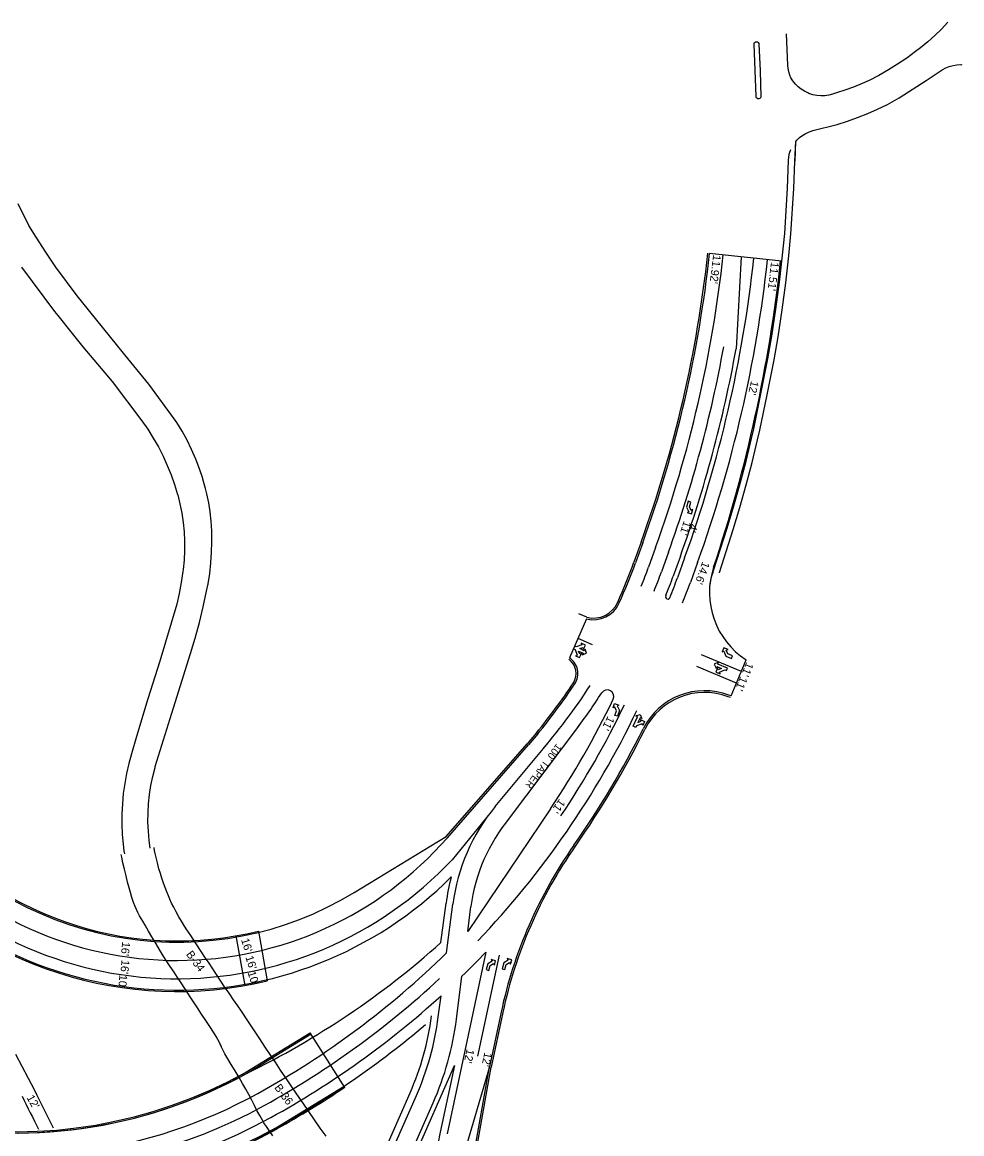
# Model space of a CAD drawing. Extents: x -5665 to 1997148, y 4 to 812485.
# Drawn here: x 1971217 to 1972039, y 796097 to 797070 of the extents above; entities that cross this region are included whole.
import ezdxf

# ---------------------------------------------------------------- set-up
doc = ezdxf.new("R2010")
doc.units = 0
for name, color, linetype in [('BR_CONCRETE', 7, 'Continuous'), ('RD_EX_Conc', 7, 'Continuous'), ('RD_EX_Road', 7, 'Continuous'), ('RD_PD_ALT1_TrvlWay', 7, 'Continuous'), ('RD_PD_Final_LnLine', 7, 'Continuous'), ('RD_PD_FOC', 7, 'Continuous'), ('RD_PD_PaintMed', 7, 'Continuous'), ('RD_PD_PaveShd', 7, 'Continuous'), ('RD_SHT_TX', 7, 'Continuous')]:
    doc.layers.add(name, color=color, linetype=linetype)

msp = doc.modelspace()

# ---------------------------------------------------------------- linework, layer by layer
at = {"layer": 'BR_CONCRETE'}
for p, q in [((1971423.24, 796274.72), (1971430.93, 796231.05)), ((1971403.67, 796270.59), (1971411.35, 796227.01)), ((1971412.3, 796151.25), (1971468.7, 796185.76)), ((1971412.98, 796150.14), (1971469.39, 796184.66)), ((1971499.08, 796137.98), (1971468.7, 796185.76)), ((1971439.09, 796102.88), (1971498.39, 796139.08))]:
    msp.add_line(p, q, dxfattribs=at)
for centre, radius, start, end in [((1971352.19, 796562.97), 296.88, 221.21202, 283.84721), ((1971352.19, 796562.97), 341.12, 221.21202, 283.34585), ((1971352.19, 796562.97), 340, 221.21202, 314.87827), ((1971210.82, 796516.01), 418, 222.88665, 298.92325), ((1971210.82, 796516.01), 416.88, 222.88665, 298.92325), ((1971051.22, 796804.85), 803.12, 298.92325, 303.88587), ((1971210.82, 796516.01), 473.13, 234.98689, 298.92325), ((1971210.82, 796516.01), 472, 234.98689, 298.92325), ((1971210.82, 796516.01), 473.3, 235.20921, 298.92325)]:
    msp.add_arc(centre, radius, start, end, dxfattribs=at)
at = {"layer": 'RD_EX_Conc'}
for points in [[(1972026.86, 797069.78), (1972021.28, 797063.78), (1972015.42, 797058.05), (1972009.29, 797052.61), (1972002.9, 797047.48), (1971998.4, 797044.15), (1971990.71, 797038.45), (1971982.79, 797033.07), (1971974.65, 797028.02), (1971966.31, 797023.31), (1971957.78, 797018.94), (1971951.78, 797016.13), (1971944.21, 797012.98), (1971936.51, 797010.2), (1971929.18, 797007.93), (1971925.88, 797006.71), (1971922.46, 797005.86), (1971918.97, 797005.4), (1971915.45, 797005.34), (1971911.95, 797005.66), (1971908.5, 797006.38), (1971905.16, 797007.48), (1971904.2, 797007.87), (1971901.14, 797009.34), (1971898.28, 797011.14), (1971895.64, 797013.27), (1971893.27, 797015.7), (1971892.25, 797017.02), (1971891.19, 797018.38), (1971889.45, 797021.28), (1971888.38, 797023.54), (1971888.38, 797023.55), (1971887.44, 797026.47), (1971886.89, 797029.48), (1971886.73, 797032.31), (1971885.52, 797059.72)], [(1971858.98, 797005.18), (1971857.2, 797050.25), (1971857.21, 797051.15), (1971857.59, 797051.95), (1971858.28, 797052.52), (1971859.15, 797052.74), (1971860.03, 797052.57), (1971860.75, 797052.04), (1971861.18, 797051.26), (1971861.26, 797050.86), (1971862.38, 797027.21), (1971862.97, 797004.54), (1971862.68, 797003.7), (1971862.05, 797003.07), (1971861.22, 797002.77), (1971860.34, 797002.85), (1971859.58, 797003.3), (1971859.08, 797004.03), (1971858.95, 797004.91), (1971858.98, 797005.18)], [(1971893.5, 796965.48), (1971892.68, 796948.33), (1971893.59, 796965.44), (1971894.61, 796966.67), (1971897, 796968.96), (1971898.86, 796970.4), (1971901.76, 796972.24), (1971904.85, 796973.73), (1971908.09, 796974.86), (1971908.46, 796974.97), (1971929.72, 796980.36), (1971938.81, 796983.14), (1971947.78, 796986.29), (1971956.61, 796989.81), (1971965.29, 796993.69), (1971973.79, 796997.94), (1971982.12, 797002.53), (1971984.25, 797003.78), (1972007.7, 797018.69), (1972021.89, 797028.21), (1972024.86, 797029.84), (1972028, 797031.12), (1972031.26, 797032.03), (1972034.61, 797032.55), (1972038, 797032.68), (1972038.93, 797032.65)], [(1971818.55, 796576.04), (1971819.11, 796580.31), (1971819.96, 796584.53), (1971821.24, 796588.64), (1971821.74, 796589.99), (1971833.45, 796627.29), (1971839.37, 796646.67), (1971844.91, 796666.17), (1971850.08, 796685.77), (1971854.86, 796705.47), (1971856.79, 796713.94), (1971863.17, 796744.61), (1971869.16, 796775.36), (1971872.82, 796795.27), (1971876.29, 796818.79), (1971879.36, 796842.37), (1971882.04, 796865.99), (1971883.92, 796885.09), (1971886.35, 796924.67), (1971887.17, 796948.68), (1971887.49, 796951.98), (1971888.14, 796955.23), (1971889.18, 796958.38)], [(1971826.86, 796588.07), (1971827, 796588.45), (1971838.76, 796625.89), (1971844.7, 796645.35), (1971850.27, 796664.94), (1971855.46, 796684.64), (1971860.26, 796704.43), (1971862.21, 796712.98), (1971868.61, 796743.73), (1971874.61, 796774.53), (1971878.28, 796794.46), (1971881.75, 796818.03), (1971884.83, 796841.7), (1971887.53, 796865.41), (1971889.42, 796884.65), (1971891.86, 796924.4), (1971892.68, 796948.33)]]:
    msp.add_lwpolyline(points, dxfattribs=at)
at = {"layer": 'RD_EX_Road'}
for points in [[(1971328.66, 796347.12), (1971327.69, 796353.97), (1971326.95, 796361.97), (1971326.61, 796370), (1971326.67, 796378.04), (1971327.12, 796386.06), (1971327.96, 796394.05), (1971329.19, 796401.99), (1971330.81, 796409.87), (1971332.82, 796417.65), (1971333.07, 796418.53), (1971348.87, 796470.12), (1971363.8, 796517.46), (1971367.92, 796530.96), (1971371.66, 796544.56), (1971375.03, 796558.26), (1971378, 796572.06), (1971379.24, 796578.41), (1971380.67, 796587.56), (1971381.72, 796596.77), (1971382.37, 796606.02), (1971382.63, 796615.28), (1971382.49, 796624.55), (1971382.23, 796629.17), (1971382, 796633.25), (1971381.13, 796641.33), (1971379.88, 796649.36), (1971378.23, 796657.31), (1971377.1, 796661.89), (1971374.75, 796670.03), (1971374.59, 796670.59), (1971371.7, 796679.17), (1971368.44, 796687.62), (1971364.81, 796695.91), (1971360.83, 796704.04), (1971356.49, 796711.99), (1971351.81, 796719.74), (1971350.55, 796721.72), (1971327.32, 796753.21), (1971306.39, 796778.94), (1971274.52, 796818.22), (1971264.73, 796830.43), (1971255.24, 796842.88), (1971246.08, 796855.57), (1971237.24, 796868.48), (1971228.73, 796881.61), (1971222.37, 796891.92), (1971213, 796910.8)], [(1971215.87, 796855.61), (1971244.73, 796816.67), (1971247.62, 796813.07), (1971260.26, 796797.37), (1971269.53, 796785.85), (1971295.21, 796755.55), (1971321.34, 796721.04), (1971326.46, 796713.65), (1971331.26, 796706.04), (1971335.71, 796698.22), (1971339.82, 796690.22), (1971343.57, 796682.04), (1971346.96, 796673.71), (1971349.98, 796665.24), (1971352.62, 796656.64), (1971352.68, 796656.43), (1971354.64, 796648.43), (1971356.22, 796640.34), (1971357.41, 796632.19), (1971358.21, 796623.98), (1971358.61, 796615.75), (1971358.62, 796607.51), (1971358.23, 796599.28), (1971357.45, 796591.07), (1971357.22, 796589.21), (1971355.78, 796579.59), (1971353.95, 796570.04), (1971351.8, 796560.8), (1971336.87, 796510.69), (1971326.57, 796477.89), (1971316.66, 796444.97), (1971312.22, 796429.78), (1971309.84, 796421.19), (1971307.85, 796412.52), (1971306.24, 796403.76), (1971305.02, 796394.93), (1971304.2, 796386.07), (1971303.76, 796377.17), (1971303.73, 796368.27), (1971304.08, 796359.37), (1971304.83, 796350.5), (1971305.51, 796344.94), (1971305.96, 796342.21)], [(1971482.56, 796095.22), (1971477.46, 796102.39), (1971472.46, 796109.55), (1971467.53, 796116.71), (1971462.36, 796124.22), (1971456.97, 796132.02), (1971451.94, 796139.39), (1971447.3, 796146.28), (1971442.71, 796153.14), (1971438.11, 796159.99), (1971433.66, 796166.64), (1971429.29, 796173.16), (1971424.49, 796180.33), (1971419.24, 796188.19), (1971413.91, 796196.2), (1971408.38, 796204.51), (1971405.15, 796209.3), (1971401.55, 796214.59), (1971397.58, 796220.38), (1971393.73, 796225.99), (1971390.5, 796230.73), (1971385.9, 796237.61), (1971382.75, 796242.42), (1971380.05, 796246.54), (1971377.11, 796251.03), (1971373.23, 796256.92), (1971368.78, 796263.66), (1971364.11, 796270.68), (1971360.11, 796276.71), (1971357.68, 796280.47), (1971355.84, 796283.47), (1971353.63, 796287.25), (1971351.31, 796291.39), (1971349.15, 796295.47), (1971347.28, 796299.24), (1971345.83, 796302.47), (1971344.52, 796305.59), (1971343.11, 796308.99), (1971341.65, 796312.69), (1971340.26, 796316.47), (1971338.77, 796320.84), (1971337.48, 796324.92), (1971336.22, 796329.28), (1971334.89, 796334.27), (1971333.72, 796338.96), (1971332.93, 796342.42), (1971332.38, 796345.2), (1971331.96, 796347.83)], [(1971436.01, 796095.53), (1971433.26, 796099.48), (1971430.34, 796103.67), (1971428.67, 796106.05), (1971428.18, 796106.82), (1971426.81, 796109.14), (1971424.43, 796113.27), (1971422.06, 796117.63), (1971419.85, 796121.99), (1971417.45, 796126.64), (1971414.83, 796131.58), (1971412.18, 796136.49), (1971409.46, 796141.39), (1971406.34, 796146.7), (1971402.85, 796152.4), (1971399.52, 796157.89), (1971396.48, 796163.01), (1971394.04, 796167.34), (1971392.22, 796170.79), (1971391, 796173.24), (1971390.3, 796174.82), (1971389.62, 796176.31), (1971388.84, 796177.9), (1971387.76, 796179.9), (1971386.26, 796182.48), (1971383.94, 796186.27), (1971380.81, 796191.24), (1971377.33, 796196.59), (1971373.61, 796202.13), (1971369.94, 796207.63), (1971366.44, 796212.91), (1971363.69, 796217.09), (1971361.58, 796220.32), (1971358.91, 796224.37), (1971355.6, 796229.33), (1971352.43, 796234.11), (1971349.44, 796238.63), (1971346.14, 796243.6), (1971342.53, 796249.07), (1971339.06, 796254.58), (1971335.81, 796260.02), (1971332.82, 796265.06), (1971330.02, 796269.77), (1971327.13, 796274.71), (1971324.21, 796279.74), (1971322.06, 796283.35), (1971320.7, 796285.58), (1971319.31, 796288), (1971317.81, 796290.81), (1971316.49, 796293.51), (1971315.35, 796296.17), (1971314.06, 796299.7), (1971312.63, 796304.09), (1971311.29, 796308.36), (1971310.07, 796312.47), (1971308.8, 796317.38), (1971307.46, 796323.11), (1971306.08, 796328.88), (1971304.73, 796334.48), (1971303.69, 796339.44), (1971303.31, 796341.64)]]:
    msp.add_lwpolyline(points, dxfattribs=at)
at = {"layer": 'RD_PD_ALT1_TrvlWay'}
for p, q in [((1971881.34, 796860.66), (1971818.2, 796867.52)), ((1971759.68, 796614.41), (1971753.4, 796596.98)), ((1971710.41, 796547.73), (1971695.48, 796513.86)), ((1971837.17, 796480.34), (1971850.32, 796511.87)), ((1971850.26, 796511.91), (1971850.32, 796511.87)), ((1971837.17, 796480.34), (1971835.07, 796481.1)), ((1971703.5, 796453.83), (1971642.9, 796373.35)), ((1971630.58, 796383.57), (1971677.08, 796439.62)), ((1971667.85, 796447.28), (1971659.59, 796437.59)), ((1971588.67, 796356.4), (1971659.59, 796437.59)), ((1971678.92, 796381.72), (1971606.52, 796274.32)), ((1971626.96, 796379.05), (1971592.79, 796337.11)), ((1971587.97, 796255.56), (1971593.49, 796298.31)), ((1971606.52, 796274.32), (1971609.35, 796296.26)), ((1971622.4, 796256.2), (1971588.39, 796097.36)), ((1971596.62, 796197.58), (1971601.48, 796235.22)), ((1971580.76, 796199.63), (1971583.13, 796218.05)), ((1971635.72, 796203.77), (1971625.47, 796155.89)), ((1971625.47, 796155.89), (1971598.28, 796063.55)), ((1971463.7, 795908.76), (1971561.57, 796130.77)), ((1971478.34, 795902.3), (1971576.21, 796124.32))]:
    msp.add_line(p, q, dxfattribs=at)
for centre, radius, start, end in [((1970728.29, 796986.16), 1096.34, 340.17915, 353.7876), ((1970607.08, 796999.33), 1280.78, 341.50403, 353.78925), ((1971283.02, 796766.52), 500, 335.82729, 340.17915), ((1971888.09, 796570.81), 70, 161.50403, 237.28747), ((1971716.37, 796572.01), 25, 256.18069, 335.82729), ((1971686.46, 796500.04), 16.5, 326.55514, 56.88198), ((1971283.02, 796766.52), 500, 320.32196, 326.55514), ((1971283.02, 796766.52), 524, 322.91379, 327.25584), ((1971728.59, 796479.98), 5.75, 334.3781, 147.25584), ((1971813.84, 796424.98), 60, 69.26451, 153.52193), ((1971051.22, 796804.85), 757, 326.01649, 334.3781), ((1971051.22, 796804.85), 792, 324.93367, 333.52193), ((1971759.11, 796276.94), 167, 140.32196, 172.64958), ((1971759.11, 796276.94), 151, 140.32196, 172.64958), ((1971352.19, 796562.97), 314, 221.21202, 318.86296), ((1971352.19, 796562.97), 330, 221.21202, 316.81039), ((1972026.85, 796120.01), 400, 144.93367, 167.91315), ((1971210.82, 796516.01), 438, 216.39766, 298.92325), ((1971051.22, 796804.85), 768, 298.92325, 314.33883), ((1971051.22, 796804.85), 792, 314.00956, 316.15347), ((1971051.22, 796804.85), 792, 298.92325, 312.19164), ((1971332.81, 796231.61), 250, 336.21044, 352.64958), ((1971332.81, 796231.61), 266, 336.21044, 352.64958), ((1971210.82, 796516.01), 462, 234.98689, 298.92325), ((1972855.69, 796921.19), 1820, 205.76109, 206.77529)]:
    msp.add_arc(centre, radius, start, end, dxfattribs=at)
at = {"layer": 'RD_PD_Final_LnLine'}
for p, q in [((1971770.97, 796610.34), (1971764.69, 796592.91)), ((1971782.26, 796606.27), (1971775.98, 796588.84)), ((1971807.66, 796597.12), (1971801.38, 796579.68)), ((1971702.94, 796530.8), (1971715.3, 796525.35)), ((1971846.1, 796501.75), (1971811.2, 796516.3)), ((1971841.86, 796491.6), (1971806.96, 796506.15)), ((1971634.14, 796253.69), (1971615.18, 796165.16))]:
    msp.add_line(p, q, dxfattribs=at)
for centre, radius, start, end in [((1970728.29, 796986.16), 1108.34, 340.17915, 353.78725), ((1970728.29, 796986.16), 1147.34, 340.17915, 353.78793), ((1970728.29, 796986.16), 1120.34, 340.17915, 349.70331), ((1971283.02, 796766.52), 512, 338.20039, 340.17915), ((1971283.02, 796766.52), 524, 338.20039, 340.17915), ((1971283.02, 796766.52), 551, 338.20039, 340.17915), ((1971283.02, 796766.52), 512, 318.95532, 327.25584), ((1971051.22, 796804.85), 768, 326.01649, 334.3781), ((1971051.22, 796804.85), 780, 316.30752, 334.3781), ((1971051.22, 796804.85), 780, 305.76044, 312.8692), ((1971051.22, 796804.85), 780, 298.92325, 306.04973), ((1971051.22, 796804.85), 780, 298.92325, 306.04973), ((1971210.82, 796516.01), 450, 239.88793, 298.92325)]:
    msp.add_arc(centre, radius, start, end, dxfattribs=at)
at = {"layer": 'RD_PD_FOC'}
for p, q in [((1971758.27, 796614.92), (1971751.99, 796597.49)), ((1971710.76, 796549.19), (1971703.64, 796552.35)), ((1971836.59, 796478.95), (1971834.56, 796479.69)), ((1971666.7, 796448.25), (1971658.45, 796438.56)), ((1971587.55, 796357.39), (1971658.46, 796438.57)), ((1971507.19, 796308.45), (1971587.55, 796357.39)), ((1971637.19, 796203.46), (1971626.93, 796155.58)), ((1971610.16, 796061.51), (1971626.93, 796155.58))]:
    msp.add_line(p, q, dxfattribs=at)
for centre, radius, start, end in [((1970728.29, 796986.16), 1094.84, 340.17915, 353.7876), ((1971283.02, 796766.52), 498.5, 335.82729, 340.17915), ((1971716.37, 796572.01), 23.5, 256.18069, 335.82729), ((1971686.46, 796500.04), 15, 326.55514, 55.93916), ((1971283.02, 796766.52), 498.5, 320.32196, 326.55514), ((1971813.84, 796424.98), 58.5, 69.26451, 153.52193), ((1971051.22, 796804.85), 793.5, 324.93367, 333.52193), ((1971352.19, 796562.97), 298, 221.21202, 301.34068), ((1971352.19, 796562.97), 298, 221.21202, 301.34068), ((1972026.85, 796120.01), 398.5, 144.93367, 167.91315)]:
    msp.add_arc(centre, radius, start, end, dxfattribs=at)
at = {"layer": 'RD_PD_PaintMed'}
for p, q in [((1971845.85, 796864.5), (1971841.41, 796783.93)), ((1971792.61, 796602.54), (1971786.33, 796585.11)), ((1971796.37, 796601.18), (1971790.09, 796583.75))]:
    msp.add_line(p, q, dxfattribs=at)
for centre, radius, start, end in [((1970728.29, 796986.16), 1135.34, 340.17915, 353.78725), ((1970728.29, 796986.16), 1131.34, 340.17915, 349.70331), ((1971283.02, 796766.52), 535, 338.20039, 340.17915), ((1971283.02, 796766.52), 539, 338.20039, 340.17915), ((1971781.62, 796567.1), 2, 158.20039, 338.20039)]:
    msp.add_arc(centre, radius, start, end, dxfattribs=at)
at = {"layer": 'RD_PD_PaveShd'}
for p, q in [((1971583.08, 796264.58), (1971587.53, 796299.08)), ((1971210.72, 796166.89), (1971227.37, 796135.4)), ((1971482, 795900.69), (1971595.06, 796157.15)), ((1971595.06, 796157.15), (1971582.52, 796098.62)), ((1971602.93, 796029.49), (1971625.46, 796155.84)), ((1971458.21, 795911.18), (1971556.08, 796133.19))]:
    msp.add_line(p, q, dxfattribs=at)
for centre, radius, start, end in [((1971759.11, 796276.94), 173, 164.8896, 172.64958), ((1971210.82, 796516.01), 418, 216.39766, 298.92325), ((1971210.82, 796516.01), 418, 216.39766, 298.92325), ((1971082.15, 796825.57), 752.09, 296.09581, 311.76326), ((1971332.81, 796231.61), 244, 336.21044, 352.64958), ((1971051.22, 796804.85), 802, 298.92325, 310.27538), ((1971210.82, 796516.01), 472, 234.98689, 298.92325), ((1971210.82, 796516.01), 472, 234.98689, 298.92325), ((1972855.69, 796921.19), 1808, 205.76109, 206.92739), ((1972226.58, 795960.7), 658.66, 167.91315, 225.41147)]:
    msp.add_arc(centre, radius, start, end, dxfattribs=at)
at = {"layer": 'RD_SHT_TX'}
for p, q in [((1971799.56, 796650.65), (1971797.97, 796645.54)), ((1971797.97, 796645.54), (1971800.06, 796641.58)), ((1971801.85, 796649.94), (1971799.56, 796650.65)), ((1971800.55, 796645.76), (1971801.85, 796649.94)), ((1971802.18, 796642.69), (1971800.55, 796645.76)), ((1971800.06, 796641.58), (1971798.62, 796640.82)), ((1971798.62, 796640.82), (1971802.44, 796639.63)), ((1971803.63, 796643.45), (1971802.18, 796642.69)), ((1971802.44, 796639.63), (1971803.63, 796643.45)), ((1971700.16, 796523.81), (1971699.15, 796521.64)), ((1971699.15, 796521.64), (1971700.46, 796521.02)), ((1971701.46, 796523.22), (1971700.16, 796523.81)), ((1971700.46, 796521.02), (1971702.27, 796516.12)), ((1971706.38, 796525.03), (1971701.46, 796523.22)), ((1971704.52, 796516.95), (1971703.54, 796519.61)), ((1971703.54, 796519.61), (1971707.48, 796517.79)), ((1971704.38, 796513.88), (1971706.05, 796517.51)), ((1971704.52, 796521.79), (1971707.21, 796522.78)), ((1971708.48, 796519.97), (1971704.52, 796521.79)), ((1971706.05, 796517.51), (1971704.52, 796516.95)), ((1971709.45, 796524.88), (1971705.82, 796526.56)), ((1971705.82, 796526.56), (1971706.38, 796525.03)), ((1971707.48, 796517.79), (1971706.8, 796516.32)), ((1971706.8, 796516.32), (1971710.55, 796517.7)), ((1971707.21, 796522.78), (1971707.78, 796521.25)), ((1971707.78, 796521.25), (1971709.45, 796524.88)), ((1971709.17, 796521.45), (1971708.48, 796519.97)), ((1971710.55, 796517.7), (1971709.17, 796521.45)), ((1971830.64, 796522.55), (1971829.1, 796518.86)), ((1971829.1, 796518.86), (1971830.6, 796519.48)), ((1971830.6, 796519.48), (1971832.3, 796515.33)), ((1971834.33, 796521.01), (1971830.64, 796522.55)), ((1971832.82, 796520.39), (1971834.33, 796521.01)), ((1971834.13, 796517.17), (1971832.82, 796520.39)), ((1971838.17, 796515.49), (1971834.13, 796517.17)), ((1971702.27, 796516.12), (1971700.74, 796515.56)), ((1971700.74, 796515.56), (1971704.38, 796513.88)), ((1971826.01, 796509.83), (1971822.31, 796508.31)), ((1971822.31, 796508.31), (1971823.84, 796504.61)), ((1971825.39, 796508.33), (1971826.01, 796509.83)), ((1971833.85, 796504.8), (1971825.39, 796508.33)), ((1971832.3, 796515.33), (1971837.24, 796513.27)), ((1971837.24, 796513.27), (1971838.17, 796515.49)), ((1971825.22, 796504.86), (1971823.68, 796501.17)), ((1971823.68, 796501.17), (1971827.37, 796499.63)), ((1971823.84, 796504.61), (1971824.46, 796506.11)), ((1971824.46, 796506.11), (1971828.51, 796504.45)), ((1971825.84, 796503.35), (1971825.22, 796504.86)), ((1971828.51, 796504.45), (1971825.84, 796503.35)), ((1971826.75, 796501.13), (1971831.58, 796503.12)), ((1971827.37, 796499.63), (1971826.75, 796501.13)), ((1971831.58, 796503.12), (1971832.93, 796502.58)), ((1971832.93, 796502.58), (1971833.85, 796504.8)), ((1971733.67, 796469.91), (1971734.98, 796473.69)), ((1971735.13, 796470.62), (1971733.67, 796469.91)), ((1971734.98, 796473.69), (1971738.76, 796472.38)), ((1971736.66, 796467.5), (1971735.13, 796470.62)), ((1971738.76, 796472.38), (1971737.29, 796471.67)), ((1971737.29, 796471.67), (1971739.25, 796467.64)), ((1971735.23, 796463.37), (1971736.66, 796467.5)), ((1971737.49, 796462.58), (1971735.23, 796463.37)), ((1971739.25, 796467.64), (1971737.49, 796462.58)), ((1971751.39, 796453.82), (1971755.17, 796462.18)), ((1971753.68, 796462.85), (1971757.43, 796464.26)), ((1971755.17, 796462.18), (1971753.68, 796462.85)), ((1971757.36, 796461.19), (1971755.53, 796457.21)), ((1971758.84, 796460.52), (1971757.36, 796461.19)), ((1971757.43, 796464.26), (1971758.84, 796460.52)), ((1971758.23, 796458.23), (1971757.66, 796459.76)), ((1971757.66, 796459.76), (1971761.3, 796458.11)), ((1971753.58, 796452.83), (1971751.39, 796453.82)), ((1971754.19, 796454.14), (1971753.58, 796452.83)), ((1971759.08, 796455.99), (1971754.19, 796454.14)), ((1971755.53, 796457.21), (1971758.23, 796458.23)), ((1971759.65, 796454.47), (1971759.08, 796455.99)), ((1971761.3, 796458.11), (1971759.65, 796454.47)), ((1971624, 796246.13), (1971622.6, 796240.97)), ((1971627.89, 796248.36), (1971624, 796246.13)), ((1971626.06, 796244.56), (1971629.08, 796246.28)), ((1971630.94, 796248.73), (1971627.08, 796249.77)), ((1971627.08, 796249.77), (1971627.89, 796248.36)), ((1971629.08, 796246.28), (1971629.89, 796244.87)), ((1971629.89, 796244.87), (1971630.94, 796248.73)), ((1971638.05, 796246.95), (1971636.65, 796241.79)), ((1971641.94, 796249.18), (1971638.05, 796246.95)), ((1971638.96, 796241.16), (1971640.11, 796245.38)), ((1971640.11, 796245.38), (1971643.13, 796247.09)), ((1971644.99, 796249.54), (1971641.13, 796250.59)), ((1971641.13, 796250.59), (1971641.94, 796249.18)), ((1971643.13, 796247.09), (1971643.94, 796245.68)), ((1971643.94, 796245.68), (1971644.99, 796249.54)), ((1971622.6, 796240.97), (1971624.91, 796240.34)), ((1971624.91, 796240.34), (1971626.06, 796244.56)), ((1971636.65, 796241.79), (1971638.96, 796241.16))]:
    msp.add_line(p, q, dxfattribs=at)

# ---------------------------------------------------------------- texts
for s, height, rotation, p in [("11.92'", 7, 262.9248, (1971821.36, 796866.54)), ("11.51'", 7, 262.9248, (1971872.06, 796860.28)), ("12'", 7, 257.17368, (1971854.57, 796756.44)), ("11'", 7, 252.06847, (1971795.71, 796633.95)), ("4'", 7, 252.06847, (1971801.4, 796631.55)), ("14.6'", 7, 250.17915, (1971812.03, 796598.42)), ("11'", 7, 247.70535, (1971850.5, 796510.36)), ("11'", 7, 247.70535, (1971845.2, 796497.89)), ("11'", 7, 242.43003, (1971729.24, 796463.24)), ("100' TAPER", 6.3, 233.23285, (1971684.3, 796439.11)), ("11'", 7, 233.83231, (1971686.89, 796390.8)), ("16'", 7, 264.36418, (1971304.12, 796265.5)), ("16'", 7, 287.4859, (1971408.02, 796267.18)), ('B-34', 7, 306.39762, (1971359.67, 796254.31)), ("16'", 7, 265.02122, (1971303.52, 796249.66)), ("16'", 7, 287.4859, (1971411.81, 796251.96)), ("10'", 7, 265.02122, (1971301.68, 796236.67)), ("10'", 7, 287.4859, (1971413.76, 796238.44)), ("12'", 7, 257.91315, (1971605.66, 796171.89)), ("12'", 7, 257.91315, (1971621.18, 796168.95)), ('B-36', 7, 306.39762, (1971436.91, 796137.74)), ("12'", 7, 299.26499, (1971220.13, 796129.03))]:
    msp.add_text(s, height=height, rotation=rotation, dxfattribs=at).set_placement(p)

doc.saveas('drawing.dxf')
